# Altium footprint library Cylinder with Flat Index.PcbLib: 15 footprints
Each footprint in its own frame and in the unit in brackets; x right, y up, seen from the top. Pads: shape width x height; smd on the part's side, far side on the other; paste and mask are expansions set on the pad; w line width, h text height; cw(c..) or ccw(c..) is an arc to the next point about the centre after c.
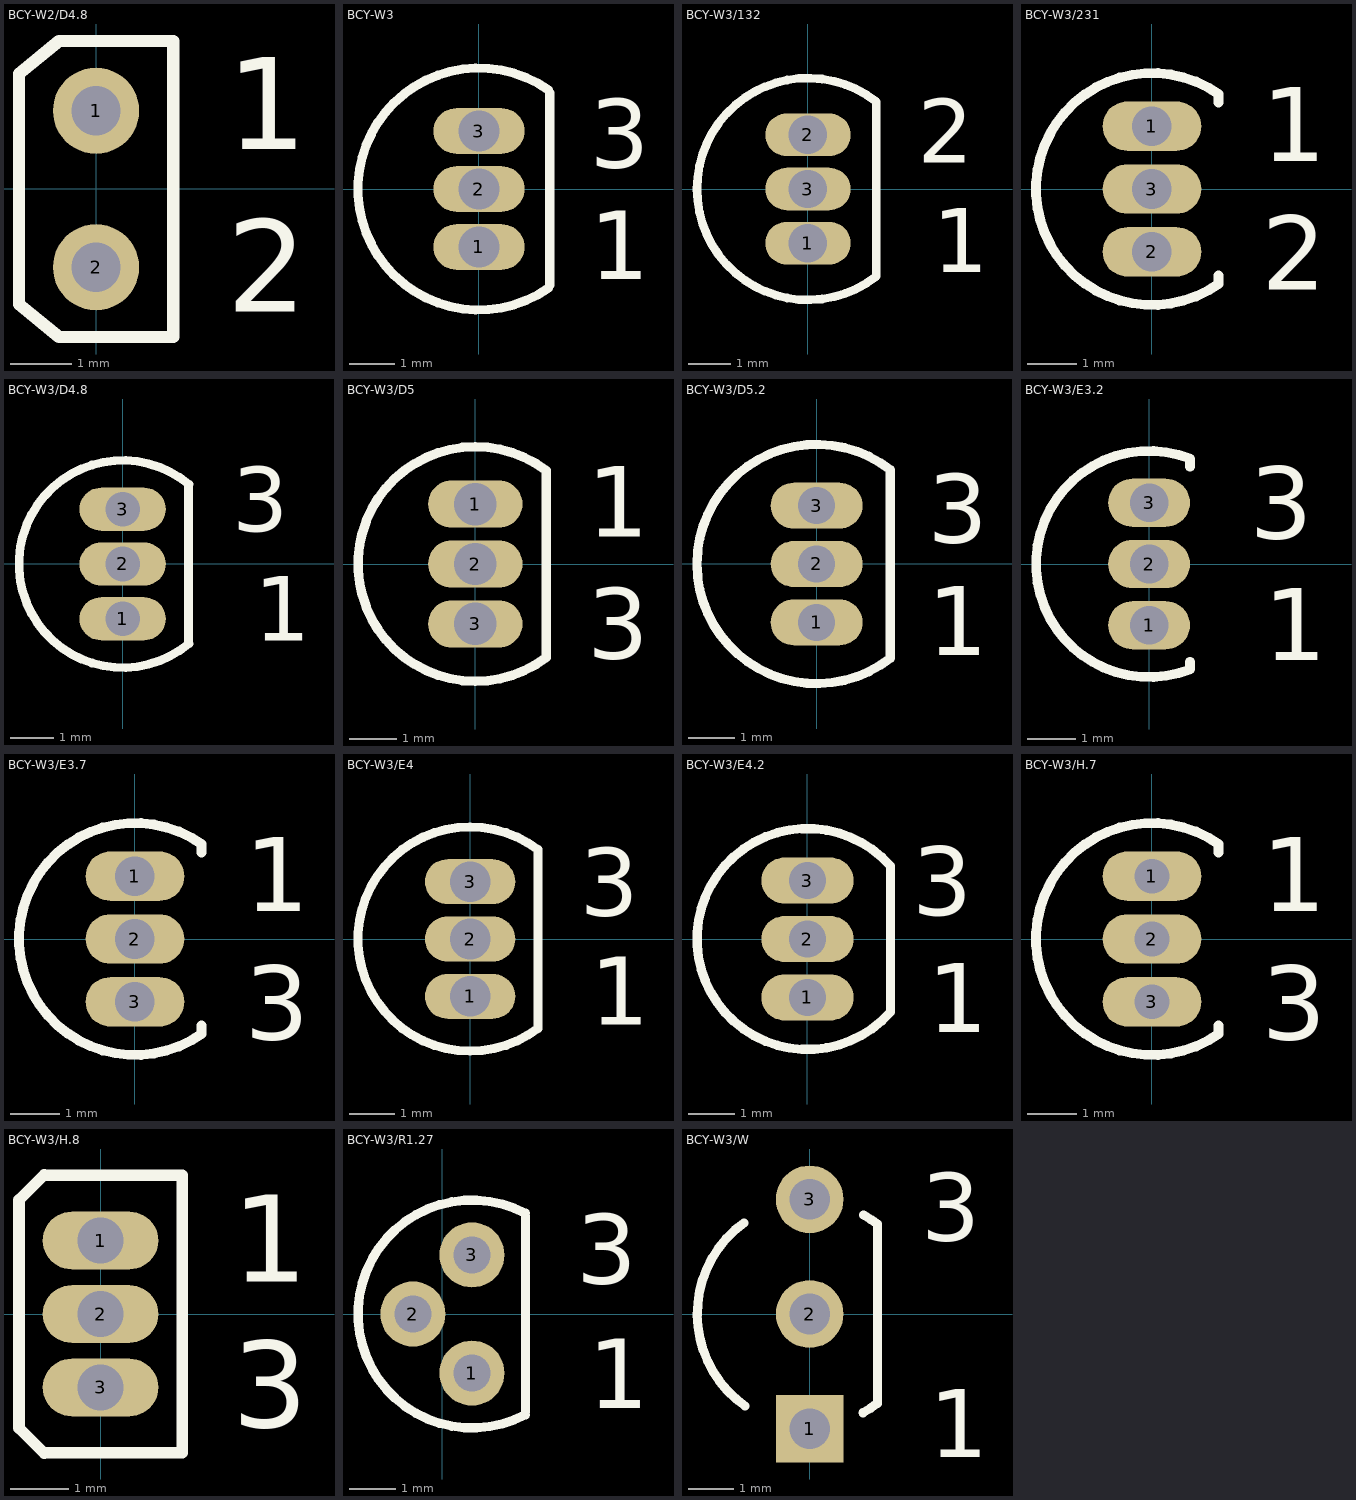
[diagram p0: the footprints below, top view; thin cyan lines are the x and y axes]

## BCY-W2/D4.8 [mm]
pads (2):
  round 1.4 hole 0.8: 1(0,1.27) 2(0,-1.27)
Top Overlay:
  lines w0.2: -1.25,-1.87 -1.25,1.87 -0.6,2.4 1.25,2.4 1.25,-2.4 -0.6,-2.4 -1.25,-1.87
  text "1" at 2.117,0.647 h1.5
  text "2" at 2.117,-1.988 h1.5

## BCY-W3 [mm]
pads (3):
  oval 2x1 hole 0.9: 1(0,-1.27) 2(0,0) 3(0,1.27)
Top Overlay:
  lines w0.2: 1.52,-2.171 cw(c0,0) 1.52,2.171 ; 1.55,-2.1 1.55,2.1
  text "3" at 2.421,0.467 h1.5
  text "1" at 2.421,-1.979 h1.5

## BCY-W3/132 [mm]
pads (3):
  oval 2x1 hole 0.9: 1(0,-1.27) 2(0,1.27) 3(0,0)
Top Overlay:
  lines w0.2: 1.601,-2.049 cw(c0,0) 1.601,2.049 ; 1.6,-1.99 1.6,1.99
  text "1" at 2.93,-1.95 h1.5
  text "2" at 2.57,0.61 h1.5

## BCY-W3/231 [mm]
pads (3):
  oval 2x1 hole 0.8: 1(0,1.27) 2(0,-1.27) 3(0,0)
Top Overlay:
  lines w0.2: 1.35,-1.75 1.35,-1.92 cw(c0,0) 1.35,1.92 1.35,1.75
  text "1" at 2.224,0.56 h1.5
  text "2" at 2.224,-2.035 h1.5

## BCY-W3/D4.8 [mm]
pads (3):
  oval 2x1 hole 0.8: 1(0,-1.27) 2(0,0) 3(0,1.27)
Top Overlay:
  lines w0.2: 1.526,-1.801 1.526,1.799 ; 1.536,-1.844 cw(c0,0) 1.536,1.844
  text "1" at 3.048,-1.778 h1.5
  text "3" at 2.54,0.762 h1.5

## BCY-W3/D5 [mm]
pads (3):
  oval 2x1 hole 0.9: 1(0,1.27) 2(0,0) 3(0,-1.27)
Top Overlay:
  lines w0.2: 1.5,-1.98 cw(c0,0) 1.5,1.98 1.5,-1.98
  text "3" at 2.37,-2.007 h1.5
  text "1" at 2.37,0.575 h1.5

## BCY-W3/D5.2 [mm]
pads (3):
  oval 2x1 hole 0.8: 1(0,-1.27) 2(0,0) 3(0,1.27)
Top Overlay:
  lines w0.2: 1.601,-2.049 cw(c0,0) 1.601,2.049 ; 1.6,-1.99 1.6,1.99
  text "1" at 2.421,-1.979 h1.5
  text "3" at 2.421,0.467 h1.5

## BCY-W3/E3.2 [mm]
pads (3):
  oval 1.7x1 hole 0.8: 1(0,-1.27) 2(0,0) 3(0,1.27)
Top Overlay:
  lines w0.2: 0.85,-2.18 0.85,-2.03 ; 0.85,2.02 0.85,2.18 ; 0.853,-2.187 cw(c0,0) 0.853,2.187
  text "3" at 2.09,0.52 h1.5
  text "1" at 2.38,-2 h1.5

## BCY-W3/E3.7 [mm]
pads (3):
  oval 2x1 hole 0.8: 1(0,1.27) 2(0,0) 3(0,-1.27)
Top Overlay:
  lines w0.2: 1.35,-1.75 1.35,-1.92 cw(c0,0) 1.35,1.92 1.35,1.75
  text "3" at 2.224,-2.035 h1.5
  text "1" at 2.224,0.56 h1.5

## BCY-W3/E4 [mm]
pads (3):
  oval 2x1 hole 0.9: 1(0,-1.27) 2(0,0) 3(0,1.27)
Top Overlay:
  lines w0.2: 1.5,-1.98 cw(c0,0) 1.5,1.98 1.5,-1.98
  text "3" at 2.43,0.51 h1.5
  text "1" at 2.66,-1.9 h1.5

## BCY-W3/E4.2 [mm]
pads (3):
  oval 2x1 hole 0.8: 1(0,-1.27) 2(0,0) 3(0,1.27)
Top Overlay:
  lines w0.2: 1.8,-1.587 1.8,1.587 ; 1.8,-1.587 cw(c0,0) 1.8,1.587
  text "3" at 2.275,0.52 h1.5
  text "1" at 2.616,-2.02 h1.5

## BCY-W3/H.7 [mm]
pads (3):
  oval 2x1 hole 0.7: 1(0,1.27) 2(0,0) 3(0,-1.27)
Top Overlay:
  lines w0.2: 1.35,-1.75 1.35,-1.92 cw(c0,0) 1.35,1.92 1.35,1.75
  text "3" at 2.224,-2.035 h1.5
  text "1" at 2.224,0.56 h1.5

## BCY-W3/H.8 [mm]
pads (3):
  oval 2x1 hole 0.8: 1(0,1.27) 2(0,0) 3(0,-1.27)
Top Overlay:
  lines w0.2: -0.97,-2.41 -1.41,-1.97 -1.41,1.97 -0.97,2.41 ; -0.97,-2.4 1.41,-2.4 1.41,2.4 -0.97,2.4
  text "1" at 2.275,0.555 h1.5
  text "3" at 2.275,-1.963 h1.5

## BCY-W3/R1.27 [mm]
pads (3):
  round 1.4 hole 0.8: 1(0.635,-1.27) 2(-0.635,0) 3(0.635,1.27)
Top Overlay:
  lines w0.2: 1.785,-2.163 cw(c0.635,0) 1.785,2.163 ; 1.785,-2.1 1.785,2.1
  text "3" at 2.875,0.65 h1.5
  text "1" at 3.135,-2.03 h1.5

## BCY-W3/W [mm]
pads (3):
  rect 1.5x1.5 hole 0.9: 1(0,-2.54)
  round 1.5 hole 0.9: 2(0,0) 3(0,2.54)
Top Overlay:
  lines w0.2: -1.457,2.019 ccw(c0,0) -1.429,-2.039 ; 1.177,-2.188 ccw(c0,0) 1.5,-1.98 1.5,1.98 ; 1.189,2.194 cw(c0,0) 1.507,1.989
  text "3" at 2.47,1.62 h1.5
  text "1" at 2.65,-3.17 h1.5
